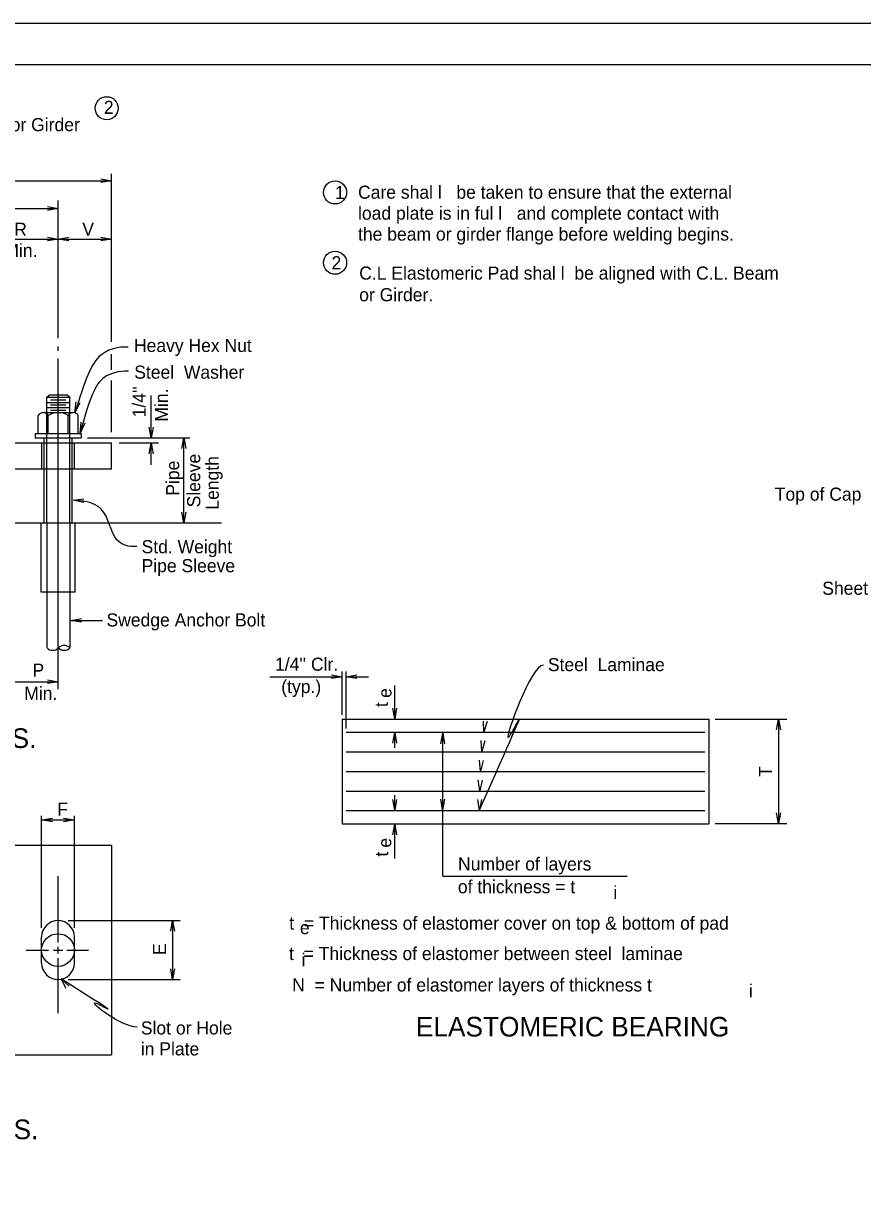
# Model space of a CAD drawing. Extents: x 113 to 232, y -103 to -27.
# Drawn here: x 154.39 to 159.73, y -35.17 to -27.79 of the extents above; entities that cross this region are included whole.
import ezdxf

# ---------------------------------------------------------------- set-up
doc = ezdxf.new("R2010")
doc.units = 0
for name, color, linetype in [('1', 7, 'Continuous'), ('B_Border', 7, 'Continuous'), ('B_Dimension', 7, 'Continuous'), ('B_No_Plot', 7, 'Continuous')]:
    doc.layers.add(name, color=color, linetype=linetype)

msp = doc.modelspace()

# ---------------------------------------------------------------- linework, layer by layer
at = {"layer": '1'}
for p, q in [((154.9532, -29.8153), (154.9532, -28.7457)), ((152.0232, -28.7904), (154.9532, -28.7904)), ((154.6132, -29.7914), (154.6132, -28.9172)), ((153.4904, -28.9671), (154.6132, -28.9671)), ((154.1147, -29.1618), (154.6132, -29.1618)), ((154.6132, -29.1618), (154.9532, -29.1618)), ((154.6132, -29.8738), (154.6132, -29.8463)), ((154.6132, -32.0263), (154.6132, -29.9208)), ((154.9532, -29.9938), (154.9532, -29.8941)), ((154.9532, -30.3906), (154.9532, -30.062)), ((154.5403, -30.1688), (154.5567, -30.1525)), ((154.5403, -30.1688), (154.6862, -30.1688)), ((154.5403, -30.266), (154.5403, -30.1688)), ((154.5403, -30.1688), (154.6862, -30.1688)), ((154.5567, -30.1525), (154.6698, -30.1525)), ((154.6698, -30.1525), (154.6862, -30.1688)), ((154.6862, -30.266), (154.6862, -30.1688)), ((155.2046, -30.427), (155.2046, -30.1581)), ((154.5403, -30.2013), (154.6862, -30.2013)), ((154.5403, -30.2336), (154.6862, -30.2336)), ((154.5647, -30.1852), (154.6618, -30.1852)), ((154.5647, -30.2176), (154.6618, -30.2176)), ((154.5647, -30.2499), (154.6618, -30.2499)), ((154.4859, -30.3998), (154.4859, -30.2843)), ((154.518, -30.266), (154.7087, -30.266)), ((154.5403, -30.9684), (154.5403, -30.266)), ((154.5502, -30.3998), (154.5502, -30.2843)), ((154.6764, -30.3998), (154.6764, -30.2843)), ((154.6862, -30.9684), (154.6862, -30.266)), ((154.741, -30.3998), (154.741, -30.2843)), ((154.4674, -30.3998), (154.7591, -30.3998)), ((154.4674, -30.3998), (154.4674, -30.4258)), ((154.7591, -30.3998), (154.7591, -30.4258)), ((152.0232, -30.4579), (154.9532, -30.4579)), ((154.4674, -30.4258), (154.7591, -30.4258)), ((154.5092, -30.6255), (154.5092, -30.4588)), ((154.5247, -30.4588), (154.5247, -30.4254)), ((154.5247, -30.6255), (154.5247, -30.4588)), ((154.7017, -30.4588), (154.7017, -30.4264)), ((154.7017, -30.6265), (154.7017, -30.4618)), ((154.7173, -30.6265), (154.7173, -30.4618)), ((154.799, -30.4258), (155.4502, -30.4258)), ((154.9532, -30.6246), (154.9532, -30.4579)), ((155.0011, -30.4579), (155.2502, -30.4579)), ((155.2046, -30.5979), (155.2046, -30.4603)), ((155.4125, -30.9684), (155.4125, -30.4258)), ((152.0232, -30.6246), (154.9532, -30.6246)), ((154.5247, -30.9684), (154.5247, -30.6255)), ((154.7017, -30.9684), (154.7017, -30.6265)), ((151.3392, -30.9684), (155.6519, -30.9684)), ((154.5047, -31.4087), (154.5047, -30.9684)), ((154.5403, -30.9684), (154.5403, -31.4087)), ((154.6862, -30.9684), (154.6862, -31.4087)), ((154.7217, -31.4087), (154.7217, -30.9684)), ((154.7217, -31.4087), (154.5047, -31.4087)), ((154.5403, -31.4087), (154.5403, -31.7618)), ((154.6862, -31.4087), (154.6862, -31.7619)), ((154.6931, -31.5884), (154.8958, -31.5884)), ((155.959, -31.9472), (156.4192, -31.9472)), ((156.4192, -32.1905), (156.4192, -31.9143)), ((156.4452, -32.2761), (156.4452, -31.9143)), ((156.4452, -31.9472), (156.5883, -31.9472)), ((154.3216, -31.9787), (154.6132, -31.9787)), ((156.7544, -32.2152), (156.7544, -32.0033)), ((156.4192, -32.2162), (158.7526, -32.2162)), ((156.4192, -32.2162), (156.4192, -32.8828)), ((158.7526, -32.2162), (158.7526, -32.8828)), ((158.7929, -32.2162), (159.248, -32.2162)), ((159.196, -32.2162), (159.196, -32.8822)), ((156.4452, -32.2995), (158.7266, -32.2995)), ((156.7544, -32.3995), (156.7544, -32.3018)), ((157.0596, -33.2166), (157.0596, -32.3062)), ((156.4452, -32.4245), (158.7266, -32.4245)), ((156.4452, -32.5495), (158.7266, -32.5495)), ((156.4452, -32.6745), (158.7266, -32.6745)), ((156.7544, -32.7958), (156.7544, -32.7014)), ((154.5078, -33.5447), (154.5078, -32.8321)), ((154.7162, -33.5447), (154.7162, -32.8321)), ((156.4452, -32.7995), (158.7266, -32.7995)), ((154.5078, -32.8583), (154.7162, -32.8583)), ((156.4192, -32.8828), (158.7526, -32.8828)), ((156.7544, -33.1037), (156.7544, -32.8852)), ((158.7929, -32.8822), (159.248, -32.8822)), ((154.1142, -33.0199), (154.952, -33.0199)), ((154.1142, -33.0199), (154.952, -33.0199)), ((154.952, -33.0199), (154.952, -34.3533)), ((154.612, -33.6387), (154.612, -33.2159)), ((157.0596, -33.2166), (158.2338, -33.2166)), ((154.6757, -33.4991), (155.3893, -33.4991)), ((155.3408, -33.4991), (155.3408, -33.8741)), ((154.5078, -33.7699), (154.5078, -33.6033)), ((154.7162, -33.7699), (154.7162, -33.6033)), ((154.4083, -33.6866), (154.5524, -33.6866)), ((154.5837, -33.6866), (154.6428, -33.6866)), ((154.612, -33.7082), (154.612, -33.6664)), ((154.6672, -33.6866), (154.7162, -33.6866)), ((154.7162, -33.6866), (154.8061, -33.6866)), ((154.612, -34.0875), (154.612, -33.7377)), ((154.6757, -33.8741), (155.3893, -33.8741)), ((154.1107, -34.3533), (154.952, -34.3533))]:
    msp.add_line(p, q, dxfattribs=at)
msp.add_lwpolyline([(154.5067, -30.4579), (154.5067, -30.4579)], dxfattribs=at)
for centre, radius in [((154.9217, -28.3289), 0.0733), ((156.3747, -28.865), 0.0733), ((156.3747, -29.3124), 0.0733), ((154.612, -33.6866), 0.1042)]:
    msp.add_circle(centre, radius, dxfattribs=at)
for centre, radius, start, end in [((154.5181, -30.3035), 0.0375, 30.80861, 149.1914), ((154.6134, -30.384), 0.118, 57.68982, 122.31018), ((154.7087, -30.3036), 0.0376, 30.95728, 149.04272), ((154.5784, -31.7286), 0.0504, 223.71346, 316.28654), ((154.6513, -31.7983), 0.0504, 43.71346, 136.28654), ((154.6513, -31.7286), 0.0504, 223.71346, 316.28654), ((154.612, -33.6032), 0.1042, 0, 180), ((154.612, -33.7699), 0.1042, 180, 0)]:
    msp.add_arc(centre, radius, start, end, dxfattribs=at)
for points in [[(155.0582, -29.8488), (155.0415, -29.8481), (154.8543, -29.8452), (154.7835, -30.0653), (154.7189, -30.266)], [(155.0613, -30.0027), (155.045, -30.0021), (154.8676, -29.9954), (154.8066, -30.2045), (154.7522, -30.3961)], [(155.1129, -31.1187), (155.0961, -31.1199), (154.9585, -31.126), (154.9236, -30.8335), (154.7531, -30.8262), (154.7079, -30.8242)], [(157.7014, -31.8725), (157.6175, -31.8755), (157.2939, -32.793), (157.7014, -31.8725), (157.2939, -32.793)], [(155.115, -34.1768), (155.0071, -34.1738), (154.6318, -33.8702), (155.115, -34.1768), (154.6318, -33.8702)]]:
    msp.add_open_spline(points, degree=3, dxfattribs=at)
at = {"layer": 'B_Border'}
msp.add_line((150.5413, -28.0514), (171.618, -28.0514), dxfattribs=at)
at = {"layer": 'B_Dimension'}
for points in [[(154.8849, -28.7783), (154.9532, -28.7904), (154.8849, -28.8024)], [(154.5449, -28.9551), (154.6132, -28.9671), (154.5449, -28.9792)], [(154.5449, -29.1498), (154.6132, -29.1618), (154.5449, -29.1738)], [(154.6816, -29.1738), (154.6132, -29.1618), (154.6816, -29.1498)], [(154.8849, -29.1498), (154.9532, -29.1618), (154.8849, -29.1738)], [(154.7513, -30.2046), (154.7189, -30.266), (154.7284, -30.1972)], [(154.7824, -30.3337), (154.7522, -30.3961), (154.7592, -30.3271)], [(155.2166, -30.3587), (155.2046, -30.427), (155.1925, -30.3587)], [(155.1925, -30.5287), (155.2046, -30.4603), (155.2166, -30.5287)], [(155.4005, -30.4942), (155.4125, -30.4258), (155.4245, -30.4942)], [(154.7756, -30.8392), (154.7079, -30.8242), (154.7766, -30.8151)], [(155.4245, -30.9001), (155.4125, -30.9684), (155.4005, -30.9001)], [(154.7614, -31.6005), (154.6931, -31.5884), (154.7614, -31.5764)], [(156.3509, -31.9351), (156.4192, -31.9472), (156.3509, -31.9592)], [(156.5136, -31.9592), (156.4452, -31.9472), (156.5136, -31.9351)], [(154.5449, -31.9666), (154.6132, -31.9787), (154.5449, -31.9907)], [(156.7664, -32.1469), (156.7544, -32.2152), (156.7424, -32.1469)], [(157.3433, -32.2327), (157.3219, -32.2986), (157.3195, -32.2293)], [(159.1839, -32.2845), (159.196, -32.2162), (159.208, -32.2845)], [(156.7424, -32.3701), (156.7544, -32.3018), (156.7664, -32.3701)], [(157.0475, -32.3745), (157.0596, -32.3062), (157.0716, -32.3745)], [(157.3281, -32.3558), (157.308, -32.4222), (157.3042, -32.3529)], [(157.3169, -32.4803), (157.3005, -32.5477), (157.2929, -32.4787)], [(157.3096, -32.6044), (157.2963, -32.6724), (157.2855, -32.6039)], [(156.7664, -32.7274), (156.7544, -32.7958), (156.7424, -32.7274)], [(157.0712, -32.7256), (157.0592, -32.7939), (157.0471, -32.7256)], [(157.3067, -32.7283), (157.2934, -32.7964), (157.2826, -32.7278)], [(159.208, -32.8139), (159.196, -32.8822), (159.1839, -32.8139)], [(154.5761, -32.8703), (154.5078, -32.8583), (154.5761, -32.8462)], [(154.6478, -32.8462), (154.7162, -32.8583), (154.6478, -32.8703)], [(156.7424, -32.9535), (156.7544, -32.8852), (156.7664, -32.9535)], [(155.3288, -33.5674), (155.3408, -33.4991), (155.3529, -33.5674)], [(154.6645, -33.9314), (154.6318, -33.8702), (154.6835, -33.9165)], [(155.3529, -33.8058), (155.3408, -33.8741), (155.3288, -33.8058)]]:
    msp.add_lwpolyline(points, dxfattribs=at)
at = {"layer": 'B_No_Plot'}
msp.add_lwpolyline([(149.5897, -27.7878), (171.923, -27.7878), (171.923, -42.0118), (149.5897, -42.0118)], close=True, dxfattribs=at)

# ---------------------------------------------------------------- texts
at = {"layer": '1'}
for s, height, p in [('2', 0.0833, (154.9037, -28.365)), ('C.L. Beam or Girder', 0.083334, (153.7535, -28.475)), ('1', 0.0833, (156.3746, -28.9066)), ('Care shal l   be taken to ensure that the external', 0.083334, (156.5208, -28.905)), ('load plate is in ful l   and complete contact with', 0.083334, (156.5208, -29.0383)), ('R', 0.0833, (154.3333, -29.1409)), ('V', 0.0833, (154.7665, -29.1409)), ('the beam or girder flange before welding begins.', 0.083334, (156.5208, -29.1717)), ('Min.', 0.08333, (154.2705, -29.2756)), ('2', 0.0833, (156.3522, -29.3539)), ('C.L Elastomeric Pad shal l  be aligned with C.L. Beam', 0.083334, (156.5283, -29.4198)), ('or Girder.', 0.08333, (156.5283, -29.5573)), ('Heavy Hex Nut', 0.083334, (155.0952, -29.8803)), ('Steel  Washer', 0.083334, (155.0968, -30.0503)), ('Top of Cap', 0.08333, (159.1722, -30.8267)), ('Std. Weight ', 0.083334, (155.1437, -31.1611)), ('Pipe Sleeve', 0.083334, (155.1437, -31.2819)), ('Sheet Metal  Sleeve', 0.083334, (159.4745, -31.4255)), ('Swedge Anchor Bolt', 0.083334, (154.9204, -31.6271)), ('P', 0.0833, (154.4492, -31.9467)), ("1/4'' Clr.", 0.08333, (155.9928, -31.9091)), ('Steel  Laminae', 0.083334, (157.7287, -31.9115)), ('Min.', 0.08333, (154.3971, -32.0943)), ('(typ.)', 0.08333, (156.0324, -32.0513)), ('FRONT VIEW - AT BENT NOS.              ', 0.124834, (152.1191, -32.4005)), ('F', 0.0833, (154.6067, -32.8311)), ('Number of layers', 0.083334, (157.1571, -33.1803)), ('of thickness = t', 0.083334, (157.1561, -33.325)), ('i', 0.0833, (158.1455, -33.3616)), ('t  = Thickness of elastomer cover on top & bottom of pad', 0.083334, (156.0832, -33.557)), ('e', 0.0833, (156.1511, -33.5853)), ('t  = Thickness of elastomer between steel  laminae', 0.083334, (156.0818, -33.7503)), ('i', 0.0833, (156.1612, -33.791)), ('N  = Number of elastomer layers of thickness t', 0.083334, (156.1018, -33.9503)), ('i', 0.0833, (159.0078, -33.9874)), ('Slot or Hole', 0.083334, (155.1389, -34.2239)), ('ELASTOMERIC BEARING', 0.124834, (156.8888, -34.2367)), ('in Plate', 0.08333, (155.1389, -34.3572)), ('PLAN VIEW - AT BENT NOS.             ', 0.124834, (152.2702, -34.8902))]:
    msp.add_text(s, height=height, dxfattribs=at).set_placement(p)
for s, height, p in [("1/4''", 0.08333, (155.1692, -30.2964)), ('Min.', 0.08333, (155.3116, -30.3234)), ('Sleeve ', 0.08333, (155.5169, -30.8691)), ('Length', 0.08333, (155.6345, -30.8838)), ('Pipe', 0.08333, (155.383, -30.7949)), ('e', 0.0833, (156.7331, -32.0817)), ('t', 0.0833, (156.7109, -32.1401)), ('T', 0.0833, (159.1543, -32.5844)), ('e', 0.0833, (156.732, -33.0349)), ('t', 0.0833, (156.7127, -33.0917)), ('E', 0.0833, (155.2992, -33.7179))]:
    msp.add_text(s, height=height, rotation=90, dxfattribs=at).set_placement(p)

doc.saveas('drawing.dxf')
